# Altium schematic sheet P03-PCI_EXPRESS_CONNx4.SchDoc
size 386 x 246 mm
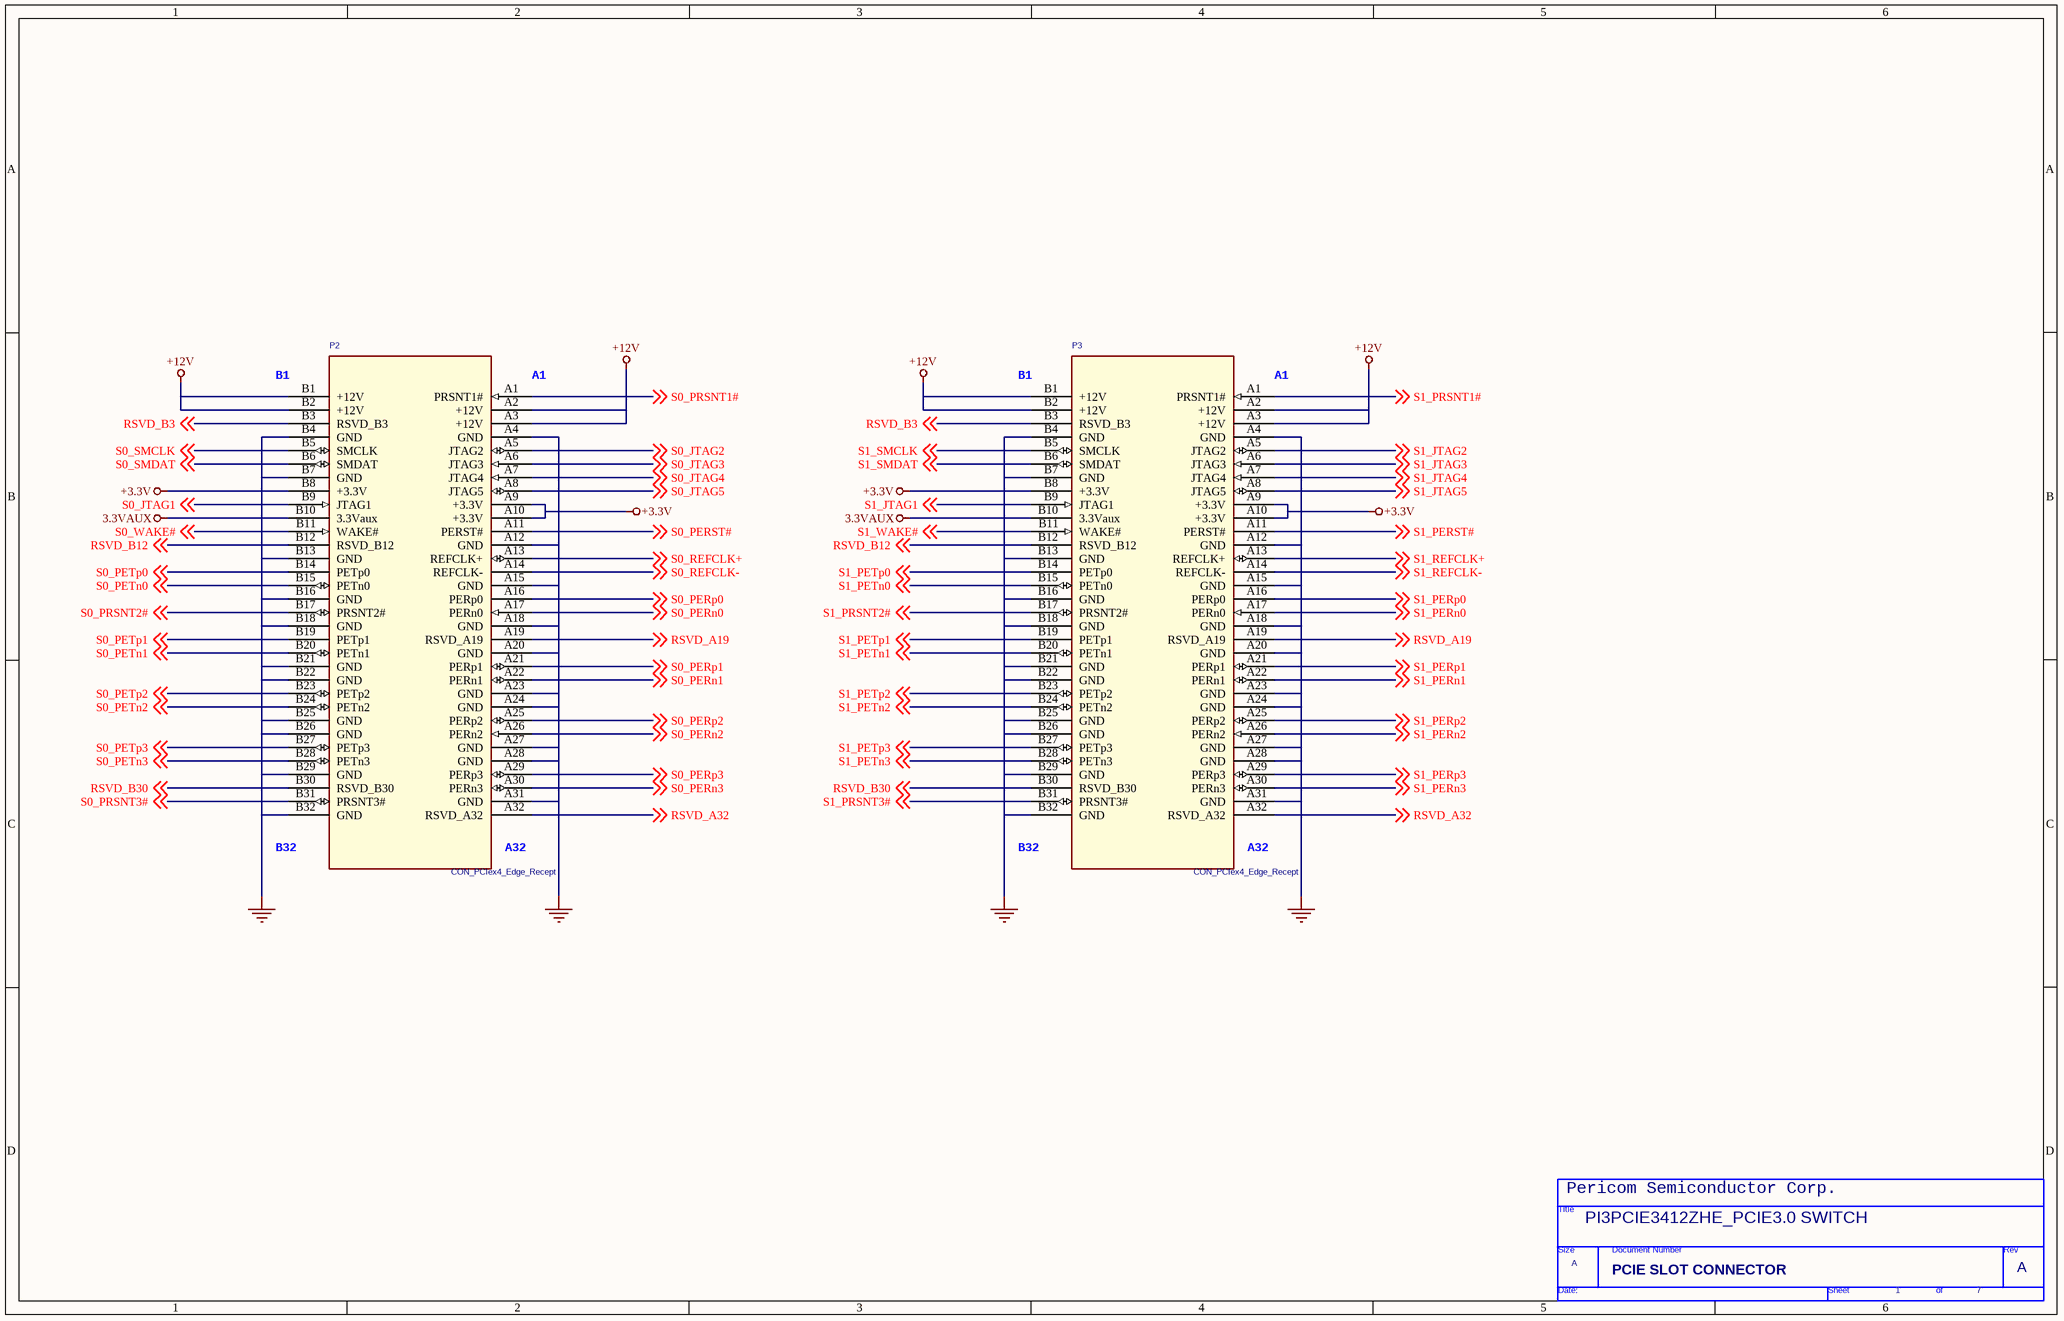
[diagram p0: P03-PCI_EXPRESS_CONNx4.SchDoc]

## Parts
*  Doc: PCIE SLOT CONNECTOR  RevCode: A  Title: PI3PCIE3412ZHE_PCIE3.0 SWITCH  Page Number: 1  Page Count: 7  (hidden comment: TitleBlock0)  (graphical)
P2  CON_PCIex4_Edge_Recept  [CON_PCIex4_Edge_Recept]
P3  CON_PCIex4_Edge_Recept  [CON_PCIex4_Edge_Recept]

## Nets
3.3VAUX: P2.B10(3.3Vaux) P3.B10(3.3Vaux)
+3.3V: P2.A9(+3.3V) P2.A10(+3.3V) P2.B8(+3.3V) P3.A9(+3.3V) P3.A10(+3.3V) P3.B8(+3.3V)
+12V: P2.A2(+12V) P2.A3(+12V) P2.B1(+12V) P2.B2(+12V) P3.A2(+12V) P3.A3(+12V) P3.B1(+12V) P3.B2(+12V)
GND: P2.A4(GND) P2.A12(GND) P2.A15(GND) P2.A18(GND) P2.A20(GND) P2.A23(GND) P2.A24(GND) P2.A27(GND) P2.A28(GND) P2.A31(GND) P2.B4(GND) P2.B7(GND) P2.B13(GND) P2.B16(GND) P2.B18(GND) P2.B21(GND) P2.B22(GND) P2.B25(GND) P2.B26(GND) P2.B29(GND) P2.B32(GND) P3.A4(GND) P3.A12(GND) P3.A15(GND) P3.A18(GND) P3.A20(GND) P3.A23(GND) P3.A24(GND) P3.A27(GND) P3.A28(GND) P3.A31(GND) P3.B4(GND) P3.B7(GND) P3.B13(GND) P3.B16(GND) P3.B18(GND) P3.B21(GND) P3.B22(GND) P3.B25(GND) P3.B26(GND) P3.B29(GND) P3.B32(GND)
RSVD_A19: P2.A19(RSVD_A19) P3.A19(RSVD_A19) ; off-sheet RSVD_A19
RSVD_A32: P2.A32(RSVD_A32) P3.A32(RSVD_A32) ; off-sheet RSVD_A32
RSVD_B3: P2.B3(RSVD_B3) P3.B3(RSVD_B3) ; off-sheet RSVD_B3
RSVD_B12: P2.B12(RSVD_B12) P3.B12(RSVD_B12) ; off-sheet RSVD_B12
RSVD_B30: P2.B30(RSVD_B30) P3.B30(RSVD_B30) ; off-sheet RSVD_B30
S0_JTAG1: P2.B9(JTAG1) ; off-sheet S0_JTAG1
S0_JTAG2: P2.A5(JTAG2) ; off-sheet S0_JTAG2
S0_JTAG3: P2.A6(JTAG3) ; off-sheet S0_JTAG3
S0_JTAG4: P2.A7(JTAG4) ; off-sheet S0_JTAG4
S0_JTAG5: P2.A8(JTAG5) ; off-sheet S0_JTAG5
S0_PERn0: P2.A17(PERn0) ; off-sheet S0_PERn0
S0_PERn1: P2.A22(PERn1) ; off-sheet S0_PERn1
S0_PERn2: P2.A26(PERn2) ; off-sheet S0_PERn2
S0_PERn3: P2.A30(PERn3) ; off-sheet S0_PERn3
S0_PERp0: P2.A16(PERp0) ; off-sheet S0_PERp0
S0_PERp1: P2.A21(PERp1) ; off-sheet S0_PERp1
S0_PERp2: P2.A25(PERp2) ; off-sheet S0_PERp2
S0_PERp3: P2.A29(PERp3) ; off-sheet S0_PERp3
S0_PERST#: P2.A11(PERST#) ; off-sheet S0_PERST#
S0_PETn0: P2.B15(PETn0) ; off-sheet S0_PETn0
S0_PETn1: P2.B20(PETn1) ; off-sheet S0_PETn1
S0_PETn2: P2.B24(PETn2) ; off-sheet S0_PETn2
S0_PETn3: P2.B28(PETn3) ; off-sheet S0_PETn3
S0_PETp0: P2.B14(PETp0) ; off-sheet S0_PETp0
S0_PETp1: P2.B19(PETp1) ; off-sheet S0_PETp1
S0_PETp2: P2.B23(PETp2) ; off-sheet S0_PETp2
S0_PETp3: P2.B27(PETp3) ; off-sheet S0_PETp3
S0_PRSNT1#: P2.A1(PRSNT1#) ; off-sheet S0_PRSNT1#
S0_PRSNT2#: P2.B17(PRSNT2#) ; off-sheet S0_PRSNT2#
S0_PRSNT3#: P2.B31(PRSNT3#) ; off-sheet S0_PRSNT3#
S0_REFCLK+: P2.A13(REFCLK+) ; off-sheet S0_REFCLK+
S0_REFCLK-: P2.A14(REFCLK-) ; off-sheet S0_REFCLK-
S0_SMCLK: P2.B5(SMCLK) ; off-sheet S0_SMCLK
S0_SMDAT: P2.B6(SMDAT) ; off-sheet S0_SMDAT
S0_WAKE#: P2.B11(WAKE#) ; off-sheet S0_WAKE#
S1_JTAG1: P3.B9(JTAG1) ; off-sheet S1_JTAG1
S1_JTAG2: P3.A5(JTAG2) ; off-sheet S1_JTAG2
S1_JTAG3: P3.A6(JTAG3) ; off-sheet S1_JTAG3
S1_JTAG4: P3.A7(JTAG4) ; off-sheet S1_JTAG4
S1_JTAG5: P3.A8(JTAG5) ; off-sheet S1_JTAG5
S1_PERn0: P3.A17(PERn0) ; off-sheet S1_PERn0
S1_PERn1: P3.A22(PERn1) ; off-sheet S1_PERn1
S1_PERn2: P3.A26(PERn2) ; off-sheet S1_PERn2
S1_PERn3: P3.A30(PERn3) ; off-sheet S1_PERn3
S1_PERp0: P3.A16(PERp0) ; off-sheet S1_PERp0
S1_PERp1: P3.A21(PERp1) ; off-sheet S1_PERp1
S1_PERp2: P3.A25(PERp2) ; off-sheet S1_PERp2
S1_PERp3: P3.A29(PERp3) ; off-sheet S1_PERp3
S1_PERST#: P3.A11(PERST#) ; off-sheet S1_PERST#
S1_PETn0: P3.B15(PETn0) ; off-sheet S1_PETn0
S1_PETn1: P3.B20(PETn1) ; off-sheet S1_PETn1
S1_PETn2: P3.B24(PETn2) ; off-sheet S1_PETn2
S1_PETn3: P3.B28(PETn3) ; off-sheet S1_PETn3
S1_PETp0: P3.B14(PETp0) ; off-sheet S1_PETp0
S1_PETp1: P3.B19(PETp1) ; off-sheet S1_PETp1
S1_PETp2: P3.B23(PETp2) ; off-sheet S1_PETp2
S1_PETp3: P3.B27(PETp3) ; off-sheet S1_PETp3
S1_PRSNT1#: P3.A1(PRSNT1#) ; off-sheet S1_PRSNT1#
S1_PRSNT2#: P3.B17(PRSNT2#) ; off-sheet S1_PRSNT2#
S1_PRSNT3#: P3.B31(PRSNT3#) ; off-sheet S1_PRSNT3#
S1_REFCLK+: P3.A13(REFCLK+) ; off-sheet S1_REFCLK+
S1_REFCLK-: P3.A14(REFCLK-) ; off-sheet S1_REFCLK-
S1_SMCLK: P3.B5(SMCLK) ; off-sheet S1_SMCLK
S1_SMDAT: P3.B6(SMDAT) ; off-sheet S1_SMDAT
S1_WAKE#: P3.B11(WAKE#) ; off-sheet S1_WAKE#

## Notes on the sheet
- (near *) Pericom Semiconductor Corp.

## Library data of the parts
P2 P3 = CON_PCIex4_Edge_Recept: SDTSourceLibName: C:\WINDOWS\TEMP\CS8.LIB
